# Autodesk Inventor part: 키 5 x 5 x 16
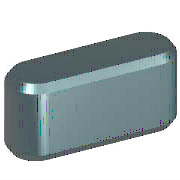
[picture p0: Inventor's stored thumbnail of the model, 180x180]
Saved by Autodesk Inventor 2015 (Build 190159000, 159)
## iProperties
IsCustomPart: 1
Created: 2012-02
Part Number: 키 5 x 5 x 16
Material: 강철, 연강
Description: 키 및 해당 키홈
Document SubType Name: Modeling
Standard: KS B 1311
Designer: mduedu
Standards Organization: KS
Language: ko-KR
Size Designation: 5 x 5 x 16
Categories: <MemberInstance><Categories><Category DisplayName="샤프트 부품" InternalName="7f7aeb1f-a693-4053-b835-cee3144e0d98" Mnemonic="SHFT"><Category DisplayName="키" Interna
Density: 1 g/cm^3
Appearance: 노란색
Author: mduedu
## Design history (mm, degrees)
workplane "Work Plane1"
workplane "Work Plane2"
sketch "스케치1"
  geometry: L1 (2.5, 2.5)-(13.5, 2.5); L2 (13.5, -2.5)-(2.5, -2.5); L3 (0, 9.4)-(0, -7.4) reference; L4 (-5, 0)-(30, 0) reference; L5 (16, 0)-(16, 7); A1 r 2.5 centre (2.5, 0) between (2.5, 2.5) and (2.5, -2.5); A2 r 2.5 centre (13.5, 0) between (13.5, -2.5) and (13.5, 2.5)
  constraints: 6 end point, 5 point on circle, 4 tangent, 3 point on line, 2 centre point, 1 horizontal, 1 parallel, 1 perpendicular
  dimensions: "d0" = 2.5 radius of A1 (= 0.5 x PB); "d13" = 2.5 radius of A2 (= 0.5 x PB); "d14" = 16 distance between parallel lines of L5 L3 (= NLG)
extrude "본체1" new body sketch "스케치1" taper "d3" = 0 deg; stored distance "d4" = 10
workplane "Work Plane3"
body "Solid1"
chamfer "모따기1" distance "d8" = 0.4 (= PHH); stored, may be unused: second distance "d9" = 0.4 (= PHH), angle "d15" = 45 deg
other parameters: "d1" = -3 (= -PNT), "d2" = 2 (= PH - PNT), "NLG" = 16 [user parameter; used in 3 equation terms], "PB" = 5 [user parameter; used in 2 equation terms], "PNT" = 3 [user parameter; used in 2 equation terms], "PH" = 5 [user parameter; used in 1 equation term], "PHH" = 0.4 [user parameter; used in 2 equation terms], "d10" = 0, "d16" = 0, "d17" = 0, "d18" = 0, "WDMIN" = 12 [user parameter], "PLB2" = 16 (= NLG) [user parameter], "WDMAX" = 17 [user parameter], "PLB1" = 16 (= NLG) [user parameter], "RR" = 0.16 [user parameter], "PUEB" = 2.3 [user parameter]
